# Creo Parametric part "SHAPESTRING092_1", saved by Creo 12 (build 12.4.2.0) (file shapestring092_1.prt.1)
Units: Custom; MM, KILOGRAM, SECS

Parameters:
  PTC_WM_ITERATION = "0"
  PTC_WM_VERSION = "-.0"
  PTC_WM_LIFECYCLE_STATE = "In Work"
  PTC_WM_LIFECYCLE = "MO_CADDocument"
  PTC_WM_CREATED_BY = "Maximilian Roepper (Z0017RMS: MO)"
  PTC_WM_CREATED_ON = "18-Sep-26 11:36:42 AM"
  PTC_WM_MODIFIED_BY = "Maximilian Roepper (Z0017RMS: MO)"
  PTC_WM_MODIFIED_ON = "18-Sep-26 11:36:46 AM"
  PDMLINKNUMBER = "PDM000071455210"
  PTC_WM_NAME = "shapestring092_1.prt"
  PTC_WM_NUMBER = "PDM000071455210"

Other parameters: WEIGHT, WEIGHT_FACTOR, WEIGHT_ADD, _MASS_TEMP, _DIFF_TEMP, MC_ERRORS, SUPPLIER

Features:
  1. coordinate system
  2. datum plane "PRT_YZ"
  3. datum plane "PRT_XY"
  4. datum plane "PRT_XZ"
  5. coordinate system
  6. datum axis
  7. datum axis
  8. datum axis
  9. coordinate system
  10. imported feature
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
Other named items: PRT, SIEMENS_MO, DRW_VIEW_ORG, PRT_X, PRT_Y, PRT_Z, CS0, ROUGH_GROB

Layers: 00_STD_CSYS-KSYS, 01_STD_PLANES-EBENEN, 02_STD_AXES-ACHSEN, 03_STD_CSYS-KSYS, 24_IMPORT_FEAT-IMPORT_KE, INTFCLR

Surfaces: 1 plane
